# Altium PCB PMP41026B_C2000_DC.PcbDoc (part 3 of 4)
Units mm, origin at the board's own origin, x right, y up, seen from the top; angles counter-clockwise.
Board outline 100 x 30 mm, 4 copper layers (Top Layer, Layer2-Plane, Layer3-Plane, Bottom Layer), stack 1.565 mm thick; 260 components, 175 nets, 797 pads, 279 vias.
Unrouted connection lines stored in the file: 19.
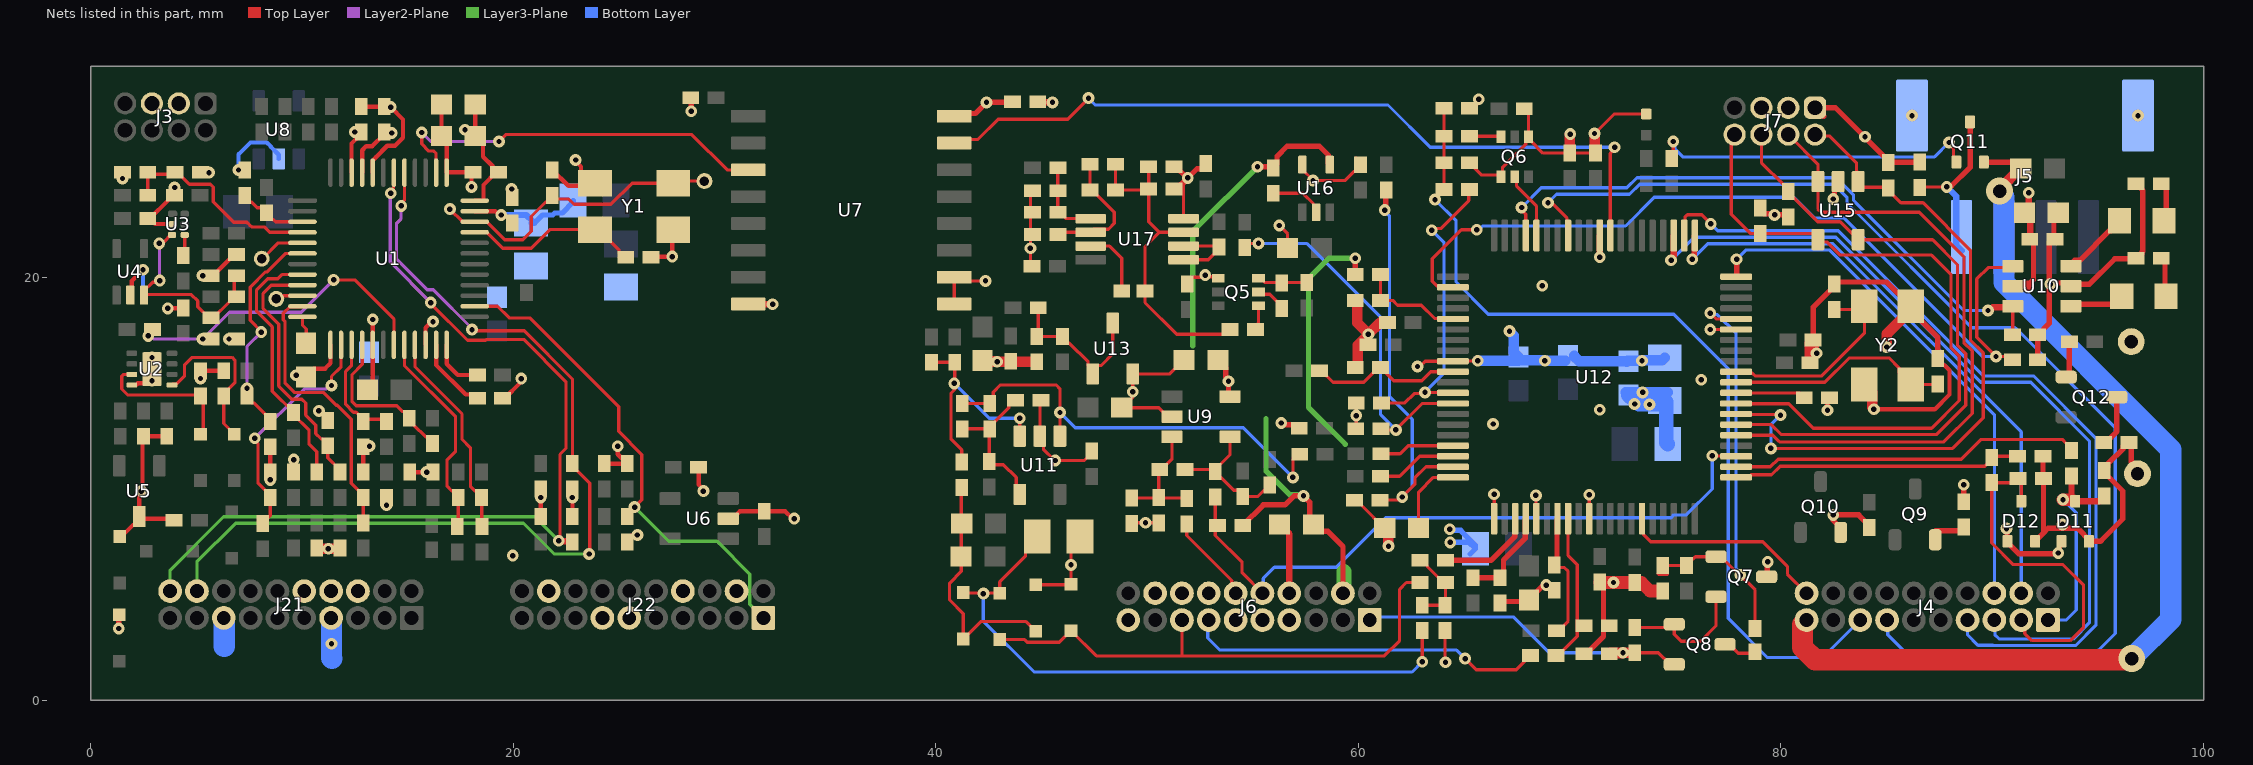
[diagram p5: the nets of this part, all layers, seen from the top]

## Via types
v1: diameter 0.559, hole 0.254, Top Layer to Bottom Layer, tented both sides, 274 vias
v2: diameter 1.27, hole 0.635, Top Layer to Bottom Layer, tented both sides, 3 vias
v3: diameter 0.559, hole 0.254, Top Layer to Bottom Layer, 2 vias

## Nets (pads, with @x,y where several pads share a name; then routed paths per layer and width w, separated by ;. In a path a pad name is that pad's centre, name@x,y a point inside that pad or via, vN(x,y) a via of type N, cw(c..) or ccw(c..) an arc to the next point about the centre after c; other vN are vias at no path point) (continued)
Input_OK: U1.38 U7.3 | length 18.8
  Top Layer w0.152: v1(15.668,26.875) 15.668,26.334 16.005,25.996 16.235,25.996 16.35,25.882 U1.38@16.35,24.975 ; v1(19.325,26.45) 19.65,26.775 28.456,26.775 30.126,25.105 U7.3@31.125,25.105
  Layer2-Plane w0.152: v1(15.668,26.875) 16.093,26.45 v1(19.325,26.45)
Iout-local: J6.13 R117.2 | length 17
  Top Layer w0.152: v1(65.05,1.975) 65.575,1.45 67.475,1.45 R117.2@68.15,2.125
  Bottom Layer w0.152: J6.13@52.92,3.8 52.875,3.755 52.875,2.95 53.449,2.376 64.649,2.376 v1(65.05,1.975)
Ip_sns/CT1: D3.2 D5.1 J6.15 R50.1 | length 25.2
  Top Layer w0.152: D3.2@43.025,2.875 44.202,2.875 44.33,2.746 45.846,2.746 D5.1@46.4,3.3 47.6,2.1 51.65,2.1 ; J6.15@51.65,3.8 51.65,2.1 ; R50.1@62.925,5.575 62.275,5.575 61.95,5.25 61.95,2.825 61.225,2.1 51.65,2.1
Ipri: C31.1 R46.2 R50.2 R77.2 | length 3.8
  Top Layer w0.152: R77.2@62.925,6.625 63.025,6.625 63.249,6.401 63.249,6.351 64.025,5.575 R50.2@64.125,5.575 64.125,4.589 64.036,4.5 R46.2@63.025,4.5
LFFET_HS: J21.20 R15.2 U1.42 | length 44.4
  Top Layer w0.152: v1(14.202,23.997) 14.202,24.107 14.339,24.244 14.339,24.964 U1.42@14.35,24.975 ; v1(16.1,18.825) 16.1,18.776 17.837,17.039 18.69,17.039 18.731,17.081 20.495,17.081 22.495,15.081 22.495,11.918 22.214,11.637 22.214,7.614 v1(22.15,7.55) ; R15.2@22.8,7.5 R15.2@22.8,7.571
  Top Layer w0.3: v1(22.15,7.55) 22.175,7.525 22.754,7.525 R15.2@22.814,7.586
  Layer2-Plane w0.152: v1(14.202,23.997) 14.175,23.97 14.175,20.75 v1(16.1,18.825)
  Layer3-Plane w0.152: J21.20@3.76,5.17 3.76,6.16 6.288,8.688 21.012,8.688 v1(22.15,7.55)
LFFET_LS: J21.18 R16.2 U1.41 | length 44.9
  Top Layer w0.152: v1(14.7,23.4) 14.7,23.51 14.85,23.66 U1.41@14.85,24.975 ; v1(18.047,17.547) 18.104,17.49 20.516,17.49 22.8,15.207 R16.2@22.8,11.2 22.8,11.1 23.625,10.275 23.625,6.931 v1@23.592,6.898
  Layer2-Plane w0.152: v1(14.7,23.4) 14.683,23.383 14.683,22.778 14.48,22.575 14.48,20.876 15.928,19.428 16.215,19.428 18.047,17.596 v1(18.047,17.547)
  Layer3-Plane w0.152: J21.18@5.03,5.17 5.03,6.555 6.858,8.383 20.484,8.383 21.942,6.925 v1(23.592,6.925)
LLC-FLT/ZCD-s: J4.13 U12.73 | length 56.6
  Top Layer w0.152: v1(68.975,23.55) 69.053,23.472 69.228,23.472 69.868,22.832 69.868,22.057 U12.73@69.925,22
  Bottom Layer w0.152: v1(68.975,23.55) 69.375,23.95 72.831,23.95 73.311,24.43 82.489,24.43 83.13,23.788 83.13,23.531 83.22,23.442 89.032,17.63 91.076,17.63 91.106,17.6 91.125,17.6 95.819,12.906 95.819,3.163 94.337,1.681 86.469,1.681 85.049,3.101 85.049,3.771 J4.13@85.02,3.8
MCU_1V2: C18.1 C19.1 C20.2 C21.2 R31.2 U1.36 U1.45 | length 10.6
  Top Layer w0.203: U1.45@12.85,24.975 12.85,26.034 13.037,26.221 13.321,26.221 13.9,26.8 C21.2@13.9,26.9 13.95,26.85 v1(14.25,26.85) ; v1(17.716,27) 17.9,27 C18.1@18.2,26.7 ; U1.36@18.175,23.65 18.57,23.65 18.591,23.671 18.591,24.391 C20.2@19.2,25 ; C19.1@18.2,28.2 C18.1@18.2,26.7 ; C20.2@19.3,25 C20.2@19.2,25 ; R31.2@19.5,14.3 19.6,14.3 20.317,15.017 20.317,15.167 v1(20.375,15.225) ; C18.1@18.2,26.7 18.225,26.7 18.573,26.352 18.573,25.727 19.027,25.273 19.027,25.173 C20.2@19.2,25
MCU_3V3: C25.1 C26.1 CP2.2 LP1.2 U1.35 U1.46 | length 8.4
  Top Layer w0.203: U1.46@12.35,24.975 12.35,26.35 C26.1@12.7,26.7 ; v1(12.5,26.9) C26.1@12.8,26.9 ; U1.35@18.175,23.15 19.155,23.15 19.337,22.968 v1(19.433,22.968) 19.529,22.968 19.599,22.898 19.752,22.898 19.95,22.7 C25.1@19.95,22.6
  Bottom Layer w0.254: CP2.2@20.838,22.588 21.003,22.588 21.385,22.97 21.87,22.97 21.967,23.067 22.326,23.067 22.834,23.575 LP1.2@22.834,23.65
  Bottom Layer w0.3: v1(19.433,22.968) 20.622,22.968 20.92,22.67 CP2.2@21.003,22.588
MCU_GPIO24: R58.2 R109.1 U12.41 | length 13.8
  Top Layer w0.152: U12.41@77.875,10.55 78.475,10.55 78.596,10.671 79.552,10.671 79.96,11.079 89.654,11.079 89.975,11.4 R109.1@89.975,11.5 ; R109.1@89.975,11.55 R58.2@91.2,11.55
MCU_GPIO31: R55.1 U10.1 U12.2 | length 39.8
  Top Layer w0.152: U12.2@64.475,19.55 64.401,19.624 63.707,19.624 63.496,19.834 63.496,20.896 64.875,22.275 v1(65.6,22.275) ; U10.1@90.806,20.481 89.806,20.481 89.269,19.944 89.269,17.181 v1(90.175,16.275) 90.8,16.275 R55.1@90.95,16.125
  Bottom Layer w0.152: v1(65.6,22.275) 65.71,22.275 65.885,22.45 72.644,22.45 73.999,23.805 80.595,23.805 81.568,22.832 82.967,22.832 89.524,16.275 v1(90.175,16.275)
MCU_GPIO32: R60.1 U12.49 | length 3.3
  Top Layer w0.152: U12.49@77.875,14.55 80.687,14.55 80.688,14.549 80.876,14.549 R60.1@81.1,14.325
MCU_GPIO34: R56.1 U10.3 U12.77 | length 29.6
  Top Layer w0.152: v1(67.725,23.325) 67.725,23.215 67.925,23.015 U12.77@67.925,22 ; R56.1@90.925,17.275 90.975,17.325 90.975,18.75 U10.3@90.95,18.775
  Top Layer w0.3: v1(89.8,18.45) 89.87,18.45 90.025,18.605 90.78,18.605 U10.3@90.95,18.775
  Bottom Layer w0.152: v1(67.725,23.325) 68.655,24.255 72.705,24.255 73.185,24.735 82.615,24.735 83.435,23.914 83.435,23.657 83.525,23.568 88.642,18.45 v1(89.8,18.45)
MCU_TCK: J7.4 U12.45 U15.3 | length 31.4
  Top Layer w0.152: U12.45@77.875,12.55 79.618,12.55 79.898,12.27 79.939,12.23 87.705,12.23 89.05,13.575 89.05,16.538 88.66,16.928 88.66,20.99 86.554,23.096 81.904,23.096 81.75,23.25 81.75,25.37 80.458,26.662 J7.4@80.345,26.775
MCU_TDI: J7.8 R73.2 U12.48 U15.4 | length 33.2
  Top Layer w0.152: J7.8@77.805,26.775 77.65,26.62 77.65,23 78.55,22.1 81.526,22.1 81.864,21.762 81.864,21.686 82.189,21.686 82.804,21.071 87.129,21.071 88.05,20.15 88.05,16.676 88.44,16.285 88.44,14.19 87.13,12.88 81.522,12.88 80.364,14.038 77.887,14.038 U12.48@77.875,14.05
MCU_TDO: J7.6 R74.2 U12.46 U15.5 | length 31
  Top Layer w0.152: U12.46@77.875,13.05 77.912,13.013 78.425,13.013 78.462,13.05 79.549,13.05 80.024,12.575 87.35,12.575 88.745,13.97 88.745,16.412 88.355,16.802 88.355,20.62 87.175,21.8 U15.5@83.65,21.8 82.8,22.65 81.745,22.65 80.35,24.045 R74.2@80.35,24.075 ; J7.6@79.075,26.775 79.075,25.452 80.126,24.401 80.126,24.399 80.257,24.268 80.259,24.268 R74.2@80.259,24.168
MCU_TMS: J7.2 R65.1 U12.47 U15.1 | length 32.7
  Top Layer w0.152: U12.47@77.875,13.55 77.9,13.525 79.95,13.525 v1(79.975,13.5) ; v1(79.525,11.925) 88.125,11.925 89.575,13.375 89.575,16.444 88.964,17.055 88.964,21.311 86.725,23.55 85.675,23.55 85.075,24.15 R65.1@85.075,24.25 ; J7.2@81.615,26.775 81.677,26.713 82.287,26.713 83.579,25.421 83.579,25.038 83.668,24.949 83.776,24.949 U15.1@83.776,24.823 ; U15.1@83.65,24.55 83.65,24.502 83.874,24.279 R65.1@85.075,24.279
  Bottom Layer w0.152: v1(79.525,11.925) 79.525,13.05 v1(79.975,13.5)
MCU_VREFHI: C59.2 U12.20 | length 3.6
  Top Layer w0.152: C59.2@62.85,8.15 62.85,9.85 63.55,10.55 U12.20@64.475,10.55
MCU_XRSn: C70.1 R61.1 U12.5 | length 5
  Top Layer w0.152: R61.1@61.05,20.15 C70.1@61.05,18.925 61.625,18.925 61.85,18.7 62.975,18.7 63.605,18.07 64.455,18.07 U12.5@64.475,18.05
NetC1_2: C1.2 U1.12 | length 1.3
  Top Layer w0.152: U1.12@10.025,18.15 10.025,17.75 10.2,17.575 C1.2@10.2,16.9
NetC2_1: C2.1 R6.1 U1.6 | length 10.5
  Top Layer w0.152: v1(7.4,14.768) 7.4,14.3 7.624,14.076 7.724,14.076 8.5,13.3 C2.1@8.5,13.2 ; v1(8.075,17.426) 8.075,17.456 7.55,17.981 7.55,19.55 8.275,20.275 8.355,20.275 9.229,21.15 U1.6@10.025,21.15
  Layer2-Plane w0.152: v1(7.4,14.768) 7.4,16.75 v1(8.075,17.426)
NetC3_1: C3.1 R7.1 U1.19 | length 15.2
  Top Layer w0.152: v1(2.725,17.25) 2.925,17.45 R7.1@2.925,17.55 ; v1(11.5,19.9) 12.5,19.9 14.35,18.05 U1.19@14.35,16.825
  Layer2-Plane w0.152: v1(2.725,17.25) 2.835,17.25 2.985,17.1 v1(5.3,17.1) 6.57,18.37 9.97,18.37 v1(11.5,19.9)
NetC4_1: C4.1 R8.1 U1.9 | length 12.3
  Top Layer w0.152: U1.9@10.025,19.65 8.55,19.65 8.159,19.26 8.159,18.539 8.899,17.8 8.899,14.872 9.517,14.254 9.995,14.254 10.175,14.073 10.175,13.5 10.65,13.025 10.65,12.625 10.901,12.374 11.001,12.374 11.225,12.15 11.225,11.475 11.8,10.9 R8.1@11.8,10.8
NetC5_1: C5.1 R10.1 U1.15 | length 5.3
  Top Layer w0.152: U1.15@12.35,16.825 12.35,15.85 12.067,15.567 12.067,14.004 12.434,13.636 12.564,13.636 12.9,13.3 C5.1@12.9,13.2 ; C5.1@12.925,13.3 13.9,13.3 R10.1@14,13.2
NetC6_2: C6.2 R5.1 U1.11 | length 13.4
  Top Layer w0.152: U1.11@10.025,18.65 10.005,18.63 9.434,18.63 9.118,18.315 9.118,18.011 9.204,17.926 9.204,14.998 9.63,14.571 11.01,14.571 11.614,13.967 11.673,13.967 12.329,13.311 12.329,10.271 12.9,9.7 R5.1@12.9,8.4
NetC7_1: C7.1 R9.1 R12.2 U1.4 | length 10
  Top Layer w0.152: R9.1@2.7,23.9 2.7,24.9 C7.1@2.7,25 ; C7.1@2.775,24.9 3.9,24.9 R12.2@4,25 4.1,25 4.671,24.429 5.67,24.429 5.804,24.295 5.804,23.596 6.771,22.629 7.395,22.629 7.529,22.495 7.618,22.405 8.214,22.405 8.468,22.15 U1.4@10.025,22.15
NetC8_1: C8.1 R11.1 U1.14 | length 11.3
  Top Layer w0.152: v1(7.768,12.4) 7.768,12.29 7.925,12.133 7.925,10.275 8.5,9.7 8.5,8.725 R11.1@8.15,8.375 ; v1(11.4,14.9) 11.4,15.331 11.85,15.781 U1.14@11.85,16.825
  Layer2-Plane w0.152: v1(7.768,12.4) 10.099,14.731 11.121,14.731 11.29,14.9 v1(11.4,14.9)
NetC14_2: C14.2 R35.2 U1.3 | length 3.4
  Top Layer w0.152: C14.2@7.3,23.9 7.3,23.8 7.524,23.576 7.624,23.576 7.886,23.314 8.101,23.314 8.325,23.091 8.325,22.975 8.549,22.751 8.649,22.751 8.75,22.65 U1.3@10.025,22.65
NetC29_1: C29.1 R47.1 R51.2 R53.2 U9.4 | length 6.7
  Top Layer w0.152: R53.2@51.8,10.925 53.125,10.925 R51.2@53.175,10.875 ; U9.4@53.925,12.475 53.925,11.625 53.225,10.925 R51.2@53.225,10.825 54.103,9.947 54.301,9.947 54.525,9.723 C29.1@54.525,9.65 55.25,9.65 R47.1@55.8,10.2
NetC33_1: C33.1 U12.50 Y2.1 | length 10.7
  Top Layer w0.152: U12.50@77.875,15.05 82.075,15.05 83.225,16.2 85.125,16.2 85.601,15.724 85.601,15.499 Y2.1@86.15,14.95 87.4,14.95 C33.1@87.425,14.975
NetC34_1: C34.1 C35.1 D4.2 D6.1 R63.1 | length 11.6
  Top Layer w0.152: R63.1@41.225,10.075 41.2,10.05 41.2,8.375 C34.1@41.2,6.8 41.2,6.1 40.65,5.55 40.65,4.748 41.3,4.098 D4.2@41.3,2.9 42.125,3.725 44.275,3.725 D6.1@44.725,3.275
NetC36_1: C36.1 U12.51 Y2.3 | length 9.8
  Top Layer w0.152: U12.51@77.875,15.55 77.949,15.476 78.649,15.476 78.77,15.355 81.93,15.355 83.95,17.375 Y2.3@83.95,18.65 83.8,18.5 C36.1@82.525,18.5
NetC37_1: C37.1 R53.1 R57.2 R59.2 U9.3 | length 5.9
  Top Layer w0.152: R59.2@49.275,9.575 51.85,9.575 R57.2@51.875,9.55 ; C37.1@50.55,9.6 R53.1@50.55,10.875 ; R53.1@50.6,10.925 R53.1@50.55,10.875 ; U9.3@51.175,12.475 51.175,11.4 50.65,10.875 R53.1@50.55,10.875
NetC44_2: C44.2 R62.1 R63.2 U11.3 | length 10.7
  Top Layer w0.152: C44.2@39.8,16 R62.1@40.9,16 40.9,14.723 40.721,14.545 40.721,12.355 41.225,11.852 R63.2@41.225,11.275 ; U11.3@43.975,12.5 v1(43.975,13.35)
  Bottom Layer w0.152: v1(40.875,15) 42.525,13.35 v1(43.975,13.35)
NetC45_1: C45.1 R68.2 R69.2 U13.1 U13.3 | length 7.8
  Top Layer w0.152: C45.1@44.775,17.225 44.85,17.3 R69.2@44.85,18.575 ; C45.1@44.85,17.225 R68.2@46,17.225 46,17.125 46.224,16.901 46.324,16.901 47.206,16.019 47.206,15.835 47.42,15.621 U13.1@47.42,15.455 ; U13.1@47.425,15.45 47.425,15.621 47.649,15.844 47.819,15.844 48.375,16.4 U13.3@48.375,17.85
NetC47_1: C47.1 R64.1 R70.2 U11.1 | length 21.1
  Top Layer w0.152: R70.2@41.25,14.05 C47.1@42.55,14.05 42.714,14.214 42.714,14.589 43.05,14.925 45.7,14.925 45.875,14.75 v1(45.875,13.625) U11.1@45.875,12.5 ; v1(56.9,10.55) 56.901,10.551 56.901,11.426 57.125,11.65 R64.1@57.225,11.65
  Bottom Layer w0.152: v1(45.875,13.625) 46.6,12.9 54.55,12.9 v1(56.9,10.55)
NetC47_2: C47.2 R48.2 R70.1 R78.2 U11.4 | length 7.2
  Top Layer w0.152: R70.1@41.25,12.85 42.5,12.85 C47.2@42.525,12.825 ; C47.2@42.525,12.85 C47.2@42.525,12.825 ; C47.2@42.55,12.85 42.55,12.95 43.451,13.851 43.451,13.976 43.675,14.2 R78.2@43.775,14.2 ; U11.4@43.975,9.75 43.802,9.923 43.802,10.548 43.2,11.15 42.675,11.15 R48.2@42.525,11.3 C47.2@42.525,12.825
NetC60_2: C60.2 U16.2 | length 2.6
  Top Layer w0.152: C60.2@55.975,24 57.369,24 57.876,23.493 57.876,23.224 U16.2@58,23.1
NetC64_1: C64.1 R95.1 R96.1 U17.6 | length 6.2
  Top Layer w0.152: R95.1@45.775,22.05 45.875,22.15 U17.6@47.325,22.15 47.474,22.299 48.174,22.299 48.45,22.575 48.45,23.1 47.4,24.15 C64.1@47.3,24.15 R96.1@47.3,25.375
NetC64_2: C64.2 C67.1 D10.1 R87.1 R96.2 R106.2 U17.3 | length 15.6
  Top Layer w0.152: C64.2@48.5,24.15 R96.2@48.5,25.375 ; C64.2@48.513,24.162 48.525,24.15 50.025,24.15 C67.1@50.075,24.2 ; R106.2@50.075,25.25 C67.1@50.075,24.2 ; U17.3@51.725,22.15 50.575,22.15 ; R87.1@53.925,17.55 53.701,17.326 53.513,17.326 53.512,17.325 51.4,17.325 49.9,18.825 D10.1@49.9,19.375 49.9,21.475 50.575,22.15 ; C67.1@50.075,24.2 50.075,22.65 50.575,22.15
NetC65_1: C65.1 R72.2 R100.2 U17.5 | length 3.8
  Top Layer w0.152: R100.2@45.775,25.2 R72.2@45.775,23.1 45.875,23.1 46.175,22.8 U17.5@47.325,22.8
NetC71_2: C71.2 R75.1 U12.19 | length 19.6
  Top Layer w0.152: C71.2@61.025,9.475 61.925,9.475 v1(62.075,9.625) 62.676,10.226 62.676,10.526 63.2,11.05 U12.19@64.475,11.05
  Top Layer w0.254: v1(61.25,23.2) 61.287,23.237 61.287,24.112 R75.1@61.325,24.15
  Bottom Layer w0.152: v1(61.25,23.2) 61.25,23.133 61.475,22.908 61.475,14.375 62.553,13.297 62.553,10.103 v1(62.075,9.625)
NetC73_2: C73.2 R80.1 U12.13 | length 17.5
  Top Layer w0.152: R80.1@54.625,21.425 54.825,21.625 v1(55.275,21.625) ; C73.2@61.075,12.85 61.125,12.8 v1(61.775,12.8) 63.025,14.05 U12.13@64.475,14.05
  Bottom Layer w0.152: v1(55.275,21.625) 57.55,21.625 61.05,18.125 61.05,13.525 v1(61.775,12.8)
NetC74_2: C74.2 R81.1 U12.12 | length 14.7
  Top Layer w0.152: C74.2@61.1,14.075 62.199,14.075 62.642,14.518 63.093,14.518 v1(63.15,14.575) 63.163,14.563 64.462,14.563 U12.12@64.475,14.55 ; v1(63.475,22.25) 63.553,22.328 63.903,22.328 65.225,23.65 65.225,24.15 R81.1@65.25,24.175
  Bottom Layer w0.152: v1(63.15,14.575) 64.05,15.475 64.05,21.675 v1(63.475,22.25)
NetC75_2: C75.2 R83.1 U12.27 | length 6.1
  Top Layer w0.152: C75.2@69.3,6.3 69.314,6.286 69.739,6.286 69.925,6.1 69.925,3.75 R83.1@69.485,3.31
  Top Layer w0.254: C75.2@69.402,6.148 69.402,6.3 69.402,8.577 U12.27@69.425,8.6
NetC76_1: C76.1 R117.1 U12.28 | length 7.1
  Top Layer w0.152: R117.1@69.35,2.125 69.45,2.125 70.356,3.031 70.356,3.525 70.356,6.419 69.925,6.85 U12.28@69.925,8.6
NetC77_1: C77.1 R116.1 U12.24 | length 4.6
  Top Layer w0.254: R116.1@65.425,5.8 C77.1@66.7,5.8 66.865,5.965 66.865,6.641 67.902,7.677 67.902,8.577 U12.24@67.925,8.6
NetC79_1: C79.1 R114.1 U12.10 | length 7.3
  Top Layer w0.152: R114.1@58.15,15.6 58.25,15.6 58.8,15.05 60.25,15.05 60.95,15.75 C79.1@61.05,15.75 61.675,15.125 63,15.125 63.425,15.55 U12.10@64.475,15.55
NetCC1_1: CC1.1 U1.33 Y1.1 | length 8.4
  Top Layer w0.152: U1.33@18.175,22.15 18.747,22.15 19.497,21.4 20.85,21.4 21.73,22.28 23.87,22.28 Y1.1@23.875,22.275 24.05,22.275 25.001,21.324 25.001,21.199 25.225,20.975 CC1.1@25.325,20.975
NetCC2_1: CC2.1 TP3.1 U1.34 Y1.3 | length 14.6
  Top Layer w0.152: v1(17,23.25) 17.002,23.25 17.602,22.65 U1.34@18.175,22.65 18.747,22.65 19.597,21.8 20.45,21.8 20.85,22.2 20.85,22.9 21.526,23.576 21.626,23.576 CC2.1@21.85,23.8 ; CC2.1@21.85,23.9 CC2.1@21.85,23.8 ; TP3.1@29.05,24.575 27.675,24.575 Y1.3@27.575,24.475 25.623,24.475 24.623,23.475 22.875,23.475 22.626,23.724 21.926,23.724 CC2.1@21.85,23.8
NetD1_1: D1.1 R20.2 U2.3 | length 6.9
  Top Layer w0.152: U2.3@1.95,15.425 1.561,15.425 1.471,15.336 1.471,14.735 1.754,14.452 5.148,14.452 5.324,14.276 5.324,12.724 D1.1@5.2,12.6
NetD2_1: D2.1 R26.2 U2.5 | length 7.7
  Top Layer w0.152: U2.5@3.85,14.925 3.899,14.974 4.068,14.974 4.437,15.343 4.437,15.86 4.805,16.229 6.695,16.229 6.829,16.095 6.829,15.029 R26.2@6.3,14.5 ; R26.2@6.3,14.4 6.3,13.1 D2.1@6.8,12.6
NetD3_1: D3.1 D4.1 R46.1 R52.2 | length 30
  Top Layer w0.152: D4.1@41.3,5.1 41.325,5.075 D3.1@43.025,5.075 43.025,5.604 44.241,6.82 44.241,7.191 R52.2@44.8,7.75 ; R46.1@62.925,3.4 R46.1@63.025,3.3 v1(63.025,1.825)
  Bottom Layer w0.152: v1(42.25,5.05) 42.25,3.75 44.658,1.342 62.542,1.342 v1(63.025,1.825)
NetD8_1: D8.1 U10.6 | length 3.2
  Top Layer w0.254: U10.6@93.725,20.65 93.898,20.823 94.148,20.823 95.552,22.227 95.602,22.227 96.025,22.65 D8.1@96.025,22.7
NetD8_2: D8.2 R45.1 | length 1.8
  Top Layer w0.254: R45.1@98,24.45 98.071,24.45 98.244,24.277 98.244,22.931 D8.2@98.15,22.838
NetD9_1: D9.1 Q8.3 | length 1.5
  Top Layer w0.152: Q8.3@77.35,2.65 77.55,2.65 77.975,2.225 D9.1@78.65,2.225
NetD10_2: D10.2 U17.7 | length 3.3
  Top Layer w0.152: U17.7@47.325,21.5 48.225,21.5 48.8,20.925 D10.2@48.8,19.375
NetD13_1: D13.1 U10.4 | length 2.9
  Top Layer w0.254: U10.4@93.725,18.75 96.075,18.75 D13.1@96.45,19.125
NetD13_2: D13.2 R54.1 | length 1.9
  Top Layer w0.254: R54.1@98.175,20.9 98.175,19.325 D13.2@98.375,19.125
NetJ5_1: J5.1 Q11.3 R110.2 | length 8.3
  Top Layer w0.152: R110.2@86.575,24.325 86.6,24.3 v1(87.85,24.3)
  Top Layer w0.254: v1(87.85,24.3) v1@87.879,24.329 ; v1@87.908,24.358 v1@87.879,24.329 ; Q11.3@88.95,27.375 88.95,25.224 88.055,24.329 v1@87.879,24.329
  Bottom Layer w0.3: v1(87.85,24.3) 88.288,23.862 88.288,21.533 J5.1@88.55,21.271
NetQ5_1: Q5.1 R87.2 | length 1.2
  Top Layer w0.152: R87.2@54.95,17.65 55.05,17.65 55.275,17.875 Q5.1@55.275,18.675
NetQ5_2: Q5.2 R90.1 | length 1.5
  Top Layer w0.152: Q5.2@55.275,19.325 55.379,19.221 55.804,19.221 56.375,18.65 R90.1@56.375,18.55
NetQ5_3: Q5.3 R90.2 R91.1 | length 2.6
  Top Layer w0.152: Q5.3@55.275,19.975 55.365,19.975 55.565,19.775 R90.2@56.446,19.775 ; R90.2@56.246,19.975 R90.2@56.446,19.775 ; R91.1@57.55,19.775 R90.2@56.446,19.775
NetQ6_3: Q6.3 R85.1 | length 1.5
  Top Layer w0.152: R85.1@65.25,26.7 66.725,26.7 Q6.3@66.75,26.675
NetQ7_2: Q7.2 Q8.1 R89.1 | length 6.2
  Top Layer w0.152: R89.1@73.075,3.45 74.8,3.45 Q8.1@74.95,3.6 74.95,3.125 75.275,2.8 76.2,2.8 76.925,3.525 Q7.2@76.925,4.9
NetQ9_2: Q9.2 R97.1 | length 1.4
  Top Layer w0.254: Q9.2@87.325,8.025 88.477,8.025 88.65,8.198 R97.1@88.65,8.2
NetQ11_1: Q11.1 R112.1 | length 15.5
  Top Layer w0.152: v1@74.697,26.372 v1@74.822,26.372 ; R112.1@74.825,25.65 74.9,25.725 v1(74.9,26.45) ; v1(87.95,26.4) 87.95,26.325 88.168,26.108 Q11.1@88.168,25.699
  Bottom Layer w0.152: v1(74.9,26.45) 74.969,26.381 74.969,26.106 75.354,25.721 87.271,25.721 v1(87.95,26.4)
NetQ12_1: Q12.1 R113.2 | length 1.7
  Top Layer w0.254: Q12.1@93.5,15.3 93.65,15.45 R113.2@93.65,16.975
NetQ12_3: Q12.3 R111.1 | length 2.5
  Top Layer w0.254: R111.1@95.275,12.2 95.375,12.2 95.9,12.725 Q12.3@95.9,14.35
NetR1_1: R1.1 R101.1 U1.16 | length 7.7
  Top Layer w0.152: U1.16@12.85,16.825 12.85,15.9 12.371,15.421 12.371,14.13 12.561,13.941 14.484,13.941 14.751,13.674 14.851,13.674 15.075,13.45 R101.1@15.075,13.35 15.075,13.25 15.299,13.026 15.851,12.474 15.951,12.474 16.175,12.25 R1.1@16.175,12.15
NetR2_1: R2.1 R102.1 U1.20 | length 10.1
  Top Layer w0.152: U1.20@14.85,16.825 14.85,15.848 17.27,13.428 17.27,11.789 16.871,11.39 16.871,10.129 17.076,9.924 17.176,9.924 17.4,9.7 17.4,8.275 R102.1@17.35,8.225
NetR3_1: R3.1 R103.1 U1.21 | length 9.9
  Top Layer w0.152: U1.21@15.35,16.825 15.35,15.779 17.575,13.554 17.575,12.35 17.971,11.954 17.971,10.129 R3.1@18.5,9.6 ; R103.1@18.513,8.237 R3.1@18.513,9.588
  Top Layer w0.254: R3.1@18.5,9.6 R3.1@18.513,9.588 ; R103.1@18.513,8.237 R103.1@18.525,8.225
NetR4_1: R4.1 R104.1 U1.8 | length 12.3
  Top Layer w0.152: U1.8@10.025,20.15 9.05,20.15 8.855,19.955 8.386,19.955 7.855,19.424 7.855,18.413 8.594,17.673 8.594,14.631 R104.1@9.6,13.625 9.6,13.525 10.336,12.789 10.336,12.12 10.696,11.76 10.696,11.555 10.7,11.552 R4.1@10.7,10.8
NetR28_1: R28.1 U3.4 | length 1
  Top Layer w0.152: R28.1@4.375,21.05 4.45,21.125 U3.4@4.45,22.025
NetR31_1: R31.1 U1.23 | length 3.6
  Top Layer w0.203: U1.23@16.35,16.825 16.35,15.875 17.75,14.475 18.125,14.475 R31.1@18.3,14.3
NetR32_1: R32.1 U1.24 | length 2.6
  Top Layer w0.203: U1.24@16.85,16.825 16.85,15.925 17.375,15.4 R32.1@18.3,15.4
NetR36_1: R36.1 R39.2 R40.1 U3.3 U4.3 | length 10.2
  Top Layer w0.152: v1(3.25,21.625) 3.328,21.703 3.478,21.703 3.8,22.025 U3.3@3.85,22.025 U3.3@3.887,22.025 ; v1(3.266,19.866) 3.188,19.788 2.938,19.788 2.525,19.375 U4.3@2.525,19.175 2.554,19.204 4.77,19.204 5.071,18.902 5.071,18.629 5.6,18.1 R39.2@5.7,18.1 5.8,18.1 6.576,18.876 6.676,18.876 R36.1@6.9,19.1 6.8,19.2 6.8,20 R40.1@6.9,20.1
  Layer2-Plane w0.152: v1(3.25,21.625) 3.258,21.617 3.258,19.874 v1(3.266,19.866)
NetR66_1: R66.1 U12.18 | length 3.8
  Top Layer w0.152: R66.1@61.05,10.6 61.95,10.6 62.9,11.55 U12.18@64.475,11.55
NetR67_1: R67.1 U12.17 | length 3.6
  Top Layer w0.152: R67.1@61.075,11.675 61.975,11.675 62.35,12.05 U12.17@64.475,12.05
NetR77_1: R77.1 U12.23 | length 4.6
  Top Layer w0.254: R77.1@64.125,6.625 66.275,6.625 67.402,7.752 67.402,8.577 U12.23@67.425,8.6
NetR99_2: R99.2 U17.1 U17.2 | length 3.8
  Top Layer w0.152: U17.1@51.725,20.85 52.9,20.85 53.4,21.35 R99.2@53.4,21.45 ; U17.2@51.725,21.5 R99.2@53.575,21.5
NetTP1_1: TP1.1 U1.10 | length 1.3
  Top Layer w0.152: TP1.1@8.788,18.999 8.95,18.999 9.101,19.15 U1.10@10.025,19.15
NetTP2_1: TP2.1 U1.5 | length 2.2
  Top Layer w0.152: TP2.1@8.094,20.904 8.134,20.904 8.879,21.65 U1.5@10.025,21.65
ORING-EN: J4.20 U12.35 | length 9.9
  Top Layer w0.152: U12.35@73.425,8.6 73.499,8.526 73.499,7.832 73.827,7.503 79.14,7.503 80.305,6.338 80.305,5.975 J4.20@81.21,5.07
PFC_OK_s: U7.15 U12.69 | length 37.3
  Top Layer w0.152: U7.15@40.875,26.375 41.048,26.548 41.998,26.548 42.95,27.5 46.25,27.5 v1@47.238,28.487 ; U12.69@71.925,22 71.925,25.883 v1@72.125,26.083
  Bottom Layer w0.152: v1(47.225,28.5) 47.55,28.175 61.4,28.175 63.4,26.175 v1(72.125,26.175)
PGND: C1.1 C2.2 C3.2 C4.2 C5.2 C6.1 C7.2 C8.2 C9.1 C10.2 C11.2 C12.2 C13.2 C14.1 C15.1 C16.2 C17.2 C18.2 C19.2 C20.1 C21.1 C22.2 C23.2 C24.1 C25.2 C26.2 C27.1 C100.2 CC1.2 CC2.2 CP1.1 CP2.1 CP3.1 CP4.1 DC3.2 DC4.2 J3.3 J3.5 J21.6 J21.7 J21.8 J21.10 J21.15 J22.4 J22.8 J22.11 J22.13 J22.18 R12.1 R13.1 R14.1 R15.1 R16.1 R17.1 R18.1 R19.1 R20.1 R22.1 R26.1 R27.1 R34.1 R40.2 R42.2 U1.13 U1.17 U1.22 U1.37 U1.44 U2.4 U2.9 U3.2 U4.2 U5.3 U6.2 U7.8 U8.2 Y1.2 Y1.4 | length 72.4
  Top Layer w0.203: DC3.2@1.375,7.75 1.573,7.948 1.648,7.948 2.002,8.302 2.102,8.302 2.3,8.5 U5.3@2.3,8.7 ; C7.2@1.5,25 1.465,24.965 1.509,24.921 v1(1.509,24.695) ; U4.2@1.875,19.15 1.948,19.223 1.948,19.848 v1(2.475,20.375) ; U2.4@1.95,14.925 1.952,14.927 2.152,14.927 2.227,15.002 2.577,15.002 2.9,15.325 U2.9@2.9,15.675 ; C15.1@2.7,22.8 C15.1@2.8,22.8 ; C17.2@3.6,12.5 R42.2@2.5,12.5 2.45,12.45 2.45,9.868 2.3,9.718 U5.3@2.3,8.7 ; v1(3.65,18.55) 4.302,18.55 4.351,18.599 C100.2@4.375,18.575 ; U3.2@3.85,22.525 3.836,22.539 3.061,22.539 C15.1@2.8,22.8 ; C16.2@3.95,8.6 2.4,8.6 U5.3@2.3,8.7 ; v1(3.975,24.268) C13.2@3.975,23.9 3.875,23.9 3.677,23.702 3.677,23.677 C15.1@2.8,22.8 ; v1(5.2,15.232) R20.1@5.2,15.6 R26.1@6.3,15.6 ; R12.1@5.2,25 5.7,25 5.675,24.975 v1(5.6,24.975) ; v1(5.3,20.1) R40.2@5.7,20.1 5.8,20.1 6.8,21.1 C11.2@6.9,21.1 ; R26.1@6.373,15.327 R26.1@6.473,15.327 ; v1(7,25.1) C14.1@7.3,25.1 ; v1(8.5,10.432) C8.2@8.5,10.8 C2.2@8.5,12 ; C10.2@9.6,10.8 9.605,10.805 9.605,11.389 v1(9.611,11.394) ; v1(9.722,15.384) 9.806,15.3 C1.1@10.2,15.3 10.2,15.325 10.573,15.698 11.098,15.698 11.35,15.95 U1.13@11.35,16.825 ; R27.1@10.7,7.2 R27.1@10.725,7.175 ; v1(10.8,13.7) 11.275,13.225 C4.2@11.4,13.225 ; C26.2@12.8,28.1 C21.1@13.9,28.1 ; C6.1@12.9,10.8 C5.2@12.9,12 ; C24.1@13.1,14.7 13.35,14.95 U1.17@13.35,16.825 v1(13.35,18.025) ; U1.44@13.35,24.975 13.35,25.549 13.49,25.689 13.49,25.696 14.04,26.246 14.4,26.246 14.783,26.629 14.783,27.492 v1(14.2,28.075) C21.1@14.175,28.1 ; v1@14,9.2 R14.1@14,9.6 14,9.7 R14.1@14.1,9.6 ; C12.2@15.1,10.8 v1(15.9,10.8) R34.1@16.2,10.8 ; U1.22@15.85,16.825 15.85,17.633 16.142,17.925 v1(16.2,17.925) ; C19.2@16.6,28.2 C18.2@16.6,26.7 16.85,26.45 U1.37@16.85,24.996 ; U1.37@16.85,24.975 U1.37@16.85,24.996 ; v1(18.025,24.3) 18.025,24.925 C20.1@18.1,25 16.854,25 U1.37@16.85,24.996 ; C25.2@19.925,23.8 v1(19.925,24.2) ; R17.1@21.3,8.7 v1(21.3,9.6) R18.1@21.3,10 ; CC2.2@21.85,25.1 22.6,24.35 23.732,24.35 Y1.4@23.857,24.475 ; R15.1@22.8,8.7 v1(22.8,9.6) R16.1@22.8,10 ; v1(22.95,25.575) 22.95,25.518 23.209,25.259 23.209,24.998 23.732,24.475 Y1.4@23.857,24.475 ; Y1.4@23.875,24.475 Y1.4@23.857,24.475 ; C9.1@24.3,11.2 R22.1@25.4,11.2 24.95,11.65 v1(24.95,12.025) ; R19.1@25.4,7.5 25.4,7.6 25.598,7.798 25.848,7.798 v1(25.875,7.825) ; CC1.2@26.525,20.975 26.537,20.987 27.512,20.987 v1(27.525,21) 27.525,22.225 Y1.2@27.575,22.275 ; v1@28.425,27.775 v1(28.425,27.884) ; C22.2@28.775,11.025 28.775,10.207 29,9.982 v1(29,9.9) ; U6.2@30.175,8.6 30.375,8.6 30.725,8.95 C23.2@31.875,8.95 32.868,8.95 33.218,8.6 v1(33.3,8.6)
  Top Layer w0.254: v1(1.325,3.4) 1.338,3.413 1.338,4.038 DC4.2@1.35,4.05 ; v1(28.425,27.884) C27.1@28.425,28.525
  Top Layer w0.3: U7.8@31.125,18.755 31.127,18.752 32.273,18.752 v1(32.275,18.75)
  Top Layer w0.5: R27.1@10.725,7.175 v1(11.25,7.175) R13.1@11.775,7.175
  Bottom Layer w0.203: v1(2.475,20.375) 2.475,19.025 2.6,18.9 ; v1(7,25.1) 7,25.84 7.564,26.404 8.336,26.404 8.529,26.211 8.529,26.196 8.9,25.825 U8.2@8.9,25.625
  Bottom Layer w1: J21.15@6.3,3.9 6.323,3.877 6.323,2.552 6.325,2.55 ; J21.7@11.38,3.9 11.403,3.877 11.403,1.997 11.425,1.975
  other v1: 11.4,2.675 19.975,6.85 14,9.232 2.4,9.9 13.2,12.032 6.55,17.1
  other v3: 2.9,15.125 2.9,16.225
PMBUS_SCL: D12.3 J4.3 R105.1 R109.2 | length 16.6
  Top Layer w0.152: R105.1@91.2,10.475 91.375,10.3 D12.3@91.375,9.425 ; R105.1@91.225,10.5 91.025,10.3 R109.2@89.975,10.3 89.975,10.2 89.975,7.446 90.996,6.425 93.35,6.425 94.325,5.45 94.325,3.464 93.686,2.825 91.875,2.825 91.54,3.16 91.54,3.63 J4.3@91.37,3.8
  Bottom Layer w0.152: J4.3@91.37,3.8 J4.3@91.555,3.615
PMBUS_SDA: D11.3 J4.1 R43.1 R108.2 | length 10.2
  Top Layer w0.152: R43.1@95.076,9.425 95.3,9.649 R43.1@95.3,9.675
  Top Layer w0.3: R108.2@93.75,10.625 93.75,9.6 D11.3@93.925,9.425 R43.1@95.076,9.425
  Top Layer w0.6: v1(93.35,9.5) D11.3@93.75,9.5
  Bottom Layer w0.152: J4.1@92.64,3.8 93.5,3.8 93.975,4.275 93.975,8.875 v1(93.35,9.5)
PMBUS_SDA-1: R108.1 U12.42 | length 16.7
  Top Layer w0.152: U12.42@77.875,11.05 79.5,11.05 79.863,11.413 88.538,11.413 89.475,12.35 93.313,12.35 93.514,12.149 93.526,12.149 93.75,11.925 R108.1@93.75,11.825
PSON#: C57.1 J4.15 R81.2 R82.1 R85.2 | length 43
  Top Layer w0.152: v1(63.625,23.7) 63.625,23.81 63.726,23.911 63.726,23.951 63.95,24.175 R81.2@64.05,24.175 R85.2@64.05,26.7 R82.1@64.05,28.025
  Bottom Layer w0.152: v1(63.625,23.7) 64.625,22.7 64.625,19.8 66.15,18.275 74.925,18.275 77.5,15.7 77.5,3.875 79.35,2.025 81.975,2.025 J4.15@83.75,3.8
PSON_CFG: Q6.5 U12.76 | length 3.2
  Top Layer w0.152: Q6.5@67.4,24.775 67.489,24.686 67.489,24.336 68.425,23.4 U12.76@68.425,22
PWM-1H-s: J4.5 U12.63 | length 39.7
  Top Layer w0.3: v1(74.8,20.825) 74.8,20.895 74.925,21.02 U12.63@74.925,22
  Bottom Layer w0.152: v1(74.8,20.825) 75.484,21.509 75.893,21.918 82.588,21.918 89.456,15.05 91.825,15.05 94.6,12.275 94.6,3.675 93.825,2.9 91,2.9 90.995,2.905 90.32,2.905 90.124,3.101 90.124,3.776 J4.5@90.1,3.8
PWM-1L-s: J4.7 U12.62 | length 41
  Top Layer w0.152: U12.62@75.425,22 75.454,22.029 75.454,22.861 75.572,22.979 76.246,22.979 v1(76.675,22.55)
  Bottom Layer w0.152: v1(76.675,22.55) 77.003,22.222 82.715,22.222 89.582,15.355 91.951,15.355 94.905,12.401 94.905,3.549 93.951,2.595 90.874,2.595 90.869,2.6 90.03,2.6 90.025,2.605 89.32,2.605 88.83,3.095 J4.7@88.83,3.8
PWM-2H-s: J4.4 U12.61 | length 28.4
  Top Layer w0.254: v1(75.8,20.875) 75.8,20.957 75.902,21.059 75.902,21.977 U12.61@75.925,22
  Bottom Layer w0.152: v1(75.8,20.875) 76.538,21.613 82.462,21.613 91.37,12.705 J4.4@91.37,5.07
PWM-2L-s: J4.6 U12.60 | length 24.9
  Top Layer w0.254: U12.60@77.875,20.05 77.877,20.05 77.9,20.073 v1(77.9,20.875)
  Bottom Layer w0.152: v1(77.9,20.875) 78.333,21.308 82.317,21.308 90.1,13.525 J4.6@90.1,5.07
PWOK-out: J6.1 Q8.2 R89.2 R94.2 | length 15.9
  Top Layer w0.152: R89.2@73.075,2.25 74.2,2.25 Q8.2@74.75,1.7
  Top Layer w0.5: R94.2@71.875,2.2 71.914,2.239 72.514,2.239 v1(72.525,2.25) R89.2@73.075,2.25
  Bottom Layer w0.152: J6.1@60.54,3.8 60.69,3.95 67.325,3.95 69.025,2.25 v1(72.525,2.25)
PWOK_in: D9.2 Q7.1 R92.2 R93.2 U12.56 | length 22.1
  Top Layer w0.152: R93.2@74.175,6 74.214,5.961 74.614,5.961 ; R93.2@74.4,6.375 R92.2@75.525,6.375 75.525,6.475 75.749,6.699 75.849,6.699 75.95,6.8 Q7.1@76.925,6.8 ; v1(76.65,18.325) 76.652,18.325 76.927,18.05 U12.56@77.875,18.05 U12.56@77.925,18 ; Q7.1@76.932,6.8 77.162,6.8 78.037,5.925 v1(78.075,5.925) 78.775,5.225 D9.2@78.775,3.4
  Bottom Layer w0.152: v1(76.65,18.325) 76.719,18.256 76.994,18.256 77.875,17.375 77.875,6.217 78.075,6.017 v1(78.075,5.925)
RELAY_CTRL: J22.1 R19.2 U1.26 | length 23.9
  Top Layer w0.152: U1.26@18.175,18.65 19.254,18.65 19.804,18.1 20.781,18.1 24.989,13.892 24.989,12.73 26.087,11.632 26.087,9.487 v1(25.743,9.143) 25.4,8.8 R19.2@25.4,8.7 R19.2@25.4,8.6
  Layer3-Plane w0.152: v1(25.743,9.143) 27.362,7.525 29.65,7.525 31.199,5.976 31.199,4.541 J22.1@31.84,3.9
RMT_SNS: J6.12 R57.1 | length 4.2
  Top Layer w0.152: R57.1@51.875,8.35 51.875,7.8 54.005,5.67 54.005,5.255 J6.12@54.19,5.07
RTN/PS_KILL: J6.10 R49.2 R51.1 U12.43 | length 31.9
  Top Layer w0.152: R51.1@53.225,9.625 53.225,7.8 54.495,6.53 54.495,6.035 J6.10@55.46,5.07 ; v1(76.75,11.575) 76.762,11.563 77.862,11.563 U12.43@77.875,11.55
  Bottom Layer w0.152: J6.10@55.46,5.07 55.494,5.104 55.494,5.769 56.025,6.3 58.95,6.3 61.295,8.645 74.801,8.645 74.931,8.775 75.525,8.775 76.75,10 v1(76.75,11.575)
S_3V3: C28.2 C30.1 C32.2 C42.2 C56.2 C60.1 C69.2 C72.2 D11.2 D12.2 J6.4 J7.1 L1.1 L2.1 Q7.3 R43.2 R45.2 R49.1 R54.2 R55.2 R56.2 R58.1 R60.2 R61.2 R65.2 R73.1 R74.1 R82.2 R97.2 R105.2 R110.1 R111.2 TP4.1 U7.16 U9.5 U10.5 U16.4 | length 98.5
  Top Layer w0.254: U7.16@40.875,27.645 41.003,27.773 41.873,27.773 42.412,28.313 43.612,28.313 C28.2@43.625,28.325 ; C32.2@53.35,16.1 53.375,16.1 53.723,15.752 v1@53.723,15.309 ; v1(53.85,15.1) 53.85,14.45 U9.5@53.925,14.375 ; R49.1@54.525,8.275 55.5,9.25 56.525,9.25 56.95,9.675 v1(57.4,9.675) 57.702,9.373 57.702,8.473 58.178,7.997 58.553,7.997 59.27,7.28 J6.4@59.27,5.07 ; v1(55.225,25.25) 55.925,25.25 C60.1@55.975,25.2 56.148,25.373 56.148,25.748 56.625,26.225 58.15,26.225 58.577,25.798 58.577,25.423 U16.4@58.65,25.35 ; R61.2@59.85,20.15 v1(59.85,20.925) ; R82.2@65.25,28.025 65.35,28.025 65.7,28.375 v1(65.7,28.45) ; R73.1@79.025,23.3 79.025,23.2 79.198,23.027 79.648,23.027 v1(79.7,22.975) 80.25,22.975 R74.1@80.35,22.875 ; Q7.3@79.325,5.85 79.35,5.875 79.35,6.525 v1(79.375,6.55) ; J7.1@82.021,27.64 J7.1@81.615,28.045 82.58,28.045 85.075,25.55 R65.2@85.075,25.45 85.1,25.475 R110.1@86.575,25.475 ; v1(82.2,13.725) 82.2,14.225 R60.2@82.3,14.325 ; R97.2@88.65,9.4 v1(88.65,10.2) ; D12.2@92.025,7.525 92.425,7.925 ; R55.2@92.15,16.125 R56.2@92.15,17.3 92.25,17.3 92.423,17.473 92.423,17.573 92.7,17.85 v1@92.7,19.75 ; R105.2@92.375,10.55 92.325,10.5 R105.2@92.425,10.5 92.425,7.925 ; R105.2@92.4,10.525 R58.1@92.4,11.55 ; C69.2@92.925,23.35 92.925,21.875 C30.1@92.975,21.825 92.875,21.825 92.702,21.652 92.702,21.505 92.7,21.503 v1@92.7,19.75 ; R43.2@95.3,10.775 96.175,9.9 96.175,8.581 95.3,7.706 95.119,7.525 94.65,7.525 94.025,8.15 92.65,8.15 92.425,7.925 ; R43.2@95.3,10.882 95.473,11.055 95.473,11.198 96.202,11.927 96.202,12.027 96.375,12.2 R111.2@96.475,12.2 96.575,12.1 96.575,11.3 96.875,11 TP4.1@96.875,10.725 ; R45.2@96.8,24.45 97.125,24.125 97.125,21.247 97.073,21.195 97.073,21.098 96.875,20.9 95.8,20.9 94.6,19.7 93.725,19.7 93.675,19.75 v1@92.7,19.75
  Layer3-Plane w0.254: 52.166,16.784 52.166,22.192 52.299,22.325 ; 52.3,22.325 v1(55.225,25.25) ; 55.625,13.325 55.625,10.85 56.742,9.733 57.342,9.733 v1(57.4,9.675) ; J6.4@59.325,5.125 J6.4@59.384,5.184 ; 59.384,12.119 57.641,13.862 57.641,19.967 58.599,20.925 v1(59.85,20.925)
  Layer3-Plane w0.7: J6.4@59.27,5.07 59.325,5.125 59.325,6.1
  Bottom Layer w0.254: J6.4@59.27,5.07 J6.4@59.369,5.169 ; v1@64.325,7.5 v1(64.35,7.475) ; v1(64.325,8.1) 64.383,8.042 64.841,8.042 65.543,7.34 L2.1@65.543,7.175 ; v1@64.448,7.475 65.243,7.475 L2.1@65.543,7.175 ; L2.1@65.293,6.925 L2.1@65.543,7.175
  Bottom Layer w0.5: v1(73.075,14.025) 72.959,14.2 C56.2@72.775,14.45 72.65,14.575 C42.2@74.65,14.575
  Bottom Layer w0.7: C56.2@72.775,14.45 72.896,14.33 C56.2@73.075,14.33 ; C56.2@73,14.305 73.279,14.025 74.341,14.025 C42.2@74.5,14.184 74.57,14.113 74.57,12.195 L1.1@74.641,12.125
  other v1: 93.325,8.325 73.775,14 73.45,14.575 92.75,19.7 83.975,26.675 42.4,28.3
S_AGND: C28.1 C30.2 C31.2 C32.1 C33.2 C36.2 C37.2 C38.1 C39.2 C40.2 C41.2 C42.1 C43.2 C45.2 C46.1 C48.2 C49.2 C50.2 C51.2 C52.2 C53.2 C54.2 C55.2 C56.1 C57.2 C58.1 C59.1 C61.2 C62.2 C63.2 C65.2 C66.2 C67.2 C68.1 C69.1 C70.2 C71.1 C72.1 C73.1 C74.1 C75.1 C76.2 C77.2 C79.2 D5.2 D6.2 D11.1 D12.1 J4.19 J5.2 J5.5 J5.6 J6.7 J6.8 J6.9 J6.11 J6.14 J6.16 J6.18 J6.19 J7.3 J7.5 Q5.4 Q6.1 Q6.4 Q10.2 Q11.2 R44.1 R52.1 R59.1 R71.1 R72.1 R76.1 R78.1 R88.1 R93.1 R94.1 R95.2 R98.2 R106.1 TP5.1 U7.9 U7.10 U9.2 U10.2 U11.2 U12.9 U12.21 U12.25 U12.30 U12.55 U12.70 U13.2 U15.2 U16.5 U17.4 Y2.2 Y2.4 | length 178.7
  Top Layer w0.152: U7.9@40.875,18.755 U7.10@40.875,20.025 ; U7.10@41.175,19.88 41.205,19.85 v1(42.35,19.85) ; C63.2@44.55,20.55 44.475,20.625 v1(44.475,21.4) 44.475,24.025 C65.2@44.575,24.125 ; D6.2@44.725,5.475 46.375,5.475 D5.2@46.4,5.5 v1(46.4,6.409) 46.4,7.318 R52.1@46.832,7.75 ; R78.1@45.225,14.2 45.149,14.2 44.925,13.976 U11.2@44.925,12.5 45.094,12.331 45.094,11.881 45.625,11.35 v1(45.65,11.35) 47.025,11.35 47.375,11.7 C41.2@47.375,11.8 C41.2@47.375,11.825 ; C46.1@48.8,13.85 C46.1@48.825,13.85 ; R59.1@49.275,8.375 49.3,8.4 v1(49.925,8.4) C37.2@50.55,8.4 ; U9.2@51.175,13.425 50.975,13.425 50.55,13.85 C46.1@48.825,13.85 ; U17.4@51.725,22.8 51.725,24.415 51.925,24.615 v1(51.925,24.725) ; C32.1@51.75,16.1 51.725,16.1 51.075,15.45 U13.2@49.325,15.45 v1(49.325,14.6) 49.325,14.35 C46.1@48.825,13.85 ; R98.2@51.9,19.7 51.9,19.8 52.124,20.024 52.539,20.024 52.64,20.125 v1(52.75,20.125) 52.825,20.05 53.3,20.05 Q5.4@53.375,19.975 ; v1(56.25,22.475) 56.65,22.075 C62.2@56.65,21.4 ; U16.5@57.35,25.35 57.35,25.125 57.85,24.625 v1(57.85,24.6) 59.35,24.6 59.776,25.026 59.876,25.026 60.1,25.25 C61.2@60.1,25.35 60.1,25.45 C61.2@59.876,25.674 ; C71.1@59.825,9.475 59.925,9.475 60.149,9.251 60.149,9.226 61.225,8.15 C59.1@61.25,8.15 ; C73.1@59.875,12.85 59.9,12.875 v1(59.9,13.475) C74.1@59.9,14.075 ; v1(62.8,15.8) 62.91,15.8 63.16,16.05 U12.9@64.475,16.05 64.488,16.063 65.638,16.063 v1(65.65,16.075) ; C31.2@64.101,3.299 64.101,1.826 v1@64.126,1.801 ; C57.2@65.25,25.45 65.842,24.858 Q6.4@66.801,24.858 ; U12.21@66.425,8.6 v1(66.425,9.75) ; Q6.4@66.75,24.775 Q6.4@66.814,24.839 ; Q6.4@66.817,24.842 Q6.4@66.814,24.839 ; R88.1@67.85,28 68.05,27.8 Q6.1@68.05,26.675 ; Q6.1@68.127,26.454 68.12,26.474 Q6.1@68.05,26.675 ; Q6.1@68.154,26.481 68.735,25.9 C55.2@70,25.9 C51.2@71.225,25.9 ; v1(68.4,9.7) 68.412,9.688 68.412,8.613 U12.25@68.425,8.6 ; U12.30@70.925,8.6 v1(70.925,9.725) ; v1(71.175,26.825) 72.1,27.75 C68.1@73.625,27.75 ; v1(76.65,17.55) U12.55@77.875,17.55 ; Y2.2@86.425,18.925 Y2.2@86.675,18.675 ; Q6.4@66.814,24.839 66.814,25.214 67.916,26.316 67.916,26.541 Q6.1@68.05,26.675
  Top Layer w0.2: v1(84.4,13.775) 87.282,13.775 87.977,14.47 87.977,15.623 87.725,15.875 87.625,15.875 87.425,16.075 C33.2@87.425,16.175
  Top Layer w0.254: C67.2@51.275,24.2 51.375,24.2 v1@51.9,24.725 ; R106.1@51.275,25.25 51.375,25.25 v1@51.9,24.725 ; R76.1@52.775,25.4 52.775,25.332 52.602,25.159 52.359,25.159 v1(51.925,24.725) v1@51.9,24.725 ; v1(56.35,13.125) 56.432,13.125 56.509,13.048 57.027,13.048 C40.2@57.2,12.875 ; C77.2@66.7,4.6 66.775,4.675 C58.1@68.075,4.675 ; C58.1@68.075,4.75 68.075,4.775 68.696,5.396 68.83,5.396 v1(68.888,5.455) 68.971,5.455 69.052,5.373 69.127,5.373 69.3,5.2 C75.1@69.3,5.1 ; R94.1@70.663,2.213 R94.1@70.675,2.2 70.775,2.2 71.602,3.027 71.602,3.352 C76.2@71.775,3.525 ; C49.2@71.425,5.6 71.425,5.5 71.602,5.323 71.602,3.698 C76.2@71.775,3.525 ; C76.2@71.875,3.525 C76.2@71.775,3.525 ; C50.2@81.525,17.05 81.525,18.6 82.525,19.6 C36.2@82.525,19.7 82.625,19.8 85,19.8 Y2.2@86.15,18.65 86.648,18.152 86.648,17.952 87.425,17.175 C33.2@87.425,16.175 ; 81.675,16.728 C50.2@81.675,17.05 ; v1(82.475,23.725) 82.533,23.783 82.533,24.383 U15.2@82.7,24.55 ; Q10.2@82.825,7.95 82.825,8.162 82.475,8.512 v1(82.475,8.775) 83.675,8.775 84.175,8.275 R44.1@84.175,8.175 ; Q11.2@89.6,25.475 91.05,25.475 C66.2@91.35,25.175 C66.2@91.325,25.175 ; v2(90.35,24.1) v2@90.35,24.2 ; v1(90.675,8.125) 90.7,8.1 90.7,7.55 D12.1@90.725,7.525 90.725,7.46 91.239,6.946 93.096,6.946 v1(93.125,6.975) 93.183,7.033 93.183,7.433 D11.1@93.275,7.525 ; C69.1@91.525,23.075 C69.1@91.675,23.225 ; 91.685,19.612 91.685,19.648 91.95,19.913 91.95,21.652 C30.2@91.775,21.825 C30.2@91.775,21.825
  Top Layer w0.3: C28.1@44.825,28.325 44.837,28.313 45.512,28.313 v1(45.525,28.3) ; C72.1@56.275,8.325 56.3,8.325 56.699,7.926 56.699,7.901 56.73,7.87 J6.8@56.73,5.07 ; v1(71.425,20.975) U12.70@71.425,22 ; v1(91.725,24.025) 91.725,23.225 91.794,23.156 91.794,21.844 C30.2@91.775,21.825
  Top Layer w0.5: C39.2@42.2,16.075 42.239,16.036 42.889,16.036 v1(42.9,16.025) C45.2@44.775,16.025 ; C79.2@59.85,15.75 59.916,15.75 59.966,15.8 59.966,16.8 60.475,17.309 v1(60.475,17.325) ; C70.2@59.85,18.925 59.891,18.925 59.941,18.875 59.941,17.875 60.475,17.341 v1(60.475,17.325) ; C59.1@61.25,8.15 61.414,7.986 61.414,7.311 v1(61.425,7.3) ; C52.2@61.382,17.884 61.374,17.875 61.025,17.875 v1(60.475,17.325) ; C55.2@70,25.9 70.014,25.914 70.014,26.789 v1(70.025,26.8) ; v1(71.175,26.825) 71.186,26.814 71.186,25.939 C51.2@71.225,25.9 ; C54.2@81.375,15.975 C50.2@81.375,16.9 ; Y2.4@83.95,14.95 84.325,14.575 84.325,13.866 84.4,13.791 v1(84.4,13.775) ; v1(85,16.725) 85.011,16.736 85.011,17.336 86.15,18.475 Y2.2@86.15,18.65 ; v2@90.35,24.2 C66.2@91.325,25.175 ; U10.2@90.975,19.6 90.981,19.606 91.679,19.606 91.685,19.612
  Top Layer w0.6: C49.2@71.425,5.575 v1(72.075,5.575) C53.2@73.075,5.575 73.4,5.575 73.8,5.175 R93.1@74.4,5.175
  Top Layer w1: J4.19@81.21,3.8 81.21,3.768 81.025,3.583 81.025,2.507 81.611,1.921 96.473,1.921 96.527,1.975 v2(96.6,1.975)
  Layer3-Plane w1: J6.7@56.73,3.8 J6.7@56.753,3.777
  Bottom Layer w0.5: v1(65.65,16.075) 65.654,16.078 67.575,16.078 67.583,16.086 68.814,16.086 v1(68.825,16.075) 68.829,16.078 C38.1@69.8,16.078 ; v1(67.15,17.475) 67.15,17.459 67.35,17.259 67.35,16.475 C43.2@67.575,16.25 ; C38.1@70.225,16.3 70.225,16.275 70.45,16.05 C56.1@72.7,16.05 ; C56.1@72.7,16.025 72.739,16.064 73.414,16.064 v1(73.425,16.075) 73.436,16.086 74.37,16.086 C42.1@74.5,16.216
  Bottom Layer w1: v2(90.35,24.1) 90.35,24.027 90.55,23.827 90.55,19.775 98.45,11.875 98.45,3.825 v2(96.6,1.975)
  other v1: 64.125,1.8 66.375,13.075 71.425,13.75 76.225,15.175 81.687,16.428 68.7,19.625 86.2,27.675 96.9,27.675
